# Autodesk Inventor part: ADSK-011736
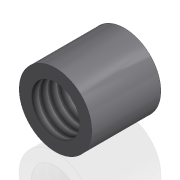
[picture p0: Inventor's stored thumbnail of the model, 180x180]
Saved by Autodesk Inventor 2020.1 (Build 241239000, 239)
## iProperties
Created: 1999-11
Part Number: ADSK-011736
Material: Acier doux
Description: HELICOIL,0.375-16NCX0.375
Document SubType Name: Modeling
Designer: lnowak
Density: 7.86 g/cm^3
Appearance: Metal-Steel(Polish)
Mass: 3.27345 g
Surface Area: 5.8451 cm^2
Volume: 0.416469 cm^3
Control State: 0
Checked Out: False
Last Check In By: lnowak
Master: False
Shininess: 0.0
Length Units: 11269
Angle Units: 11279
Time Units: 11290
Mass Units: 11283
Length Display Precision: 3
Angle Display Precision: 2
Compacted: True
Material Desc: HELICOIL, 0.375-16NC X 0.38
Material_number: A092959
Dimensions: 10x9,5x10 mm
Mass: 0,003 kg
DocNumber: ADSK-011736.ipt
Folder: 01 - Themengebiete\Simplification\01 - Packaging machine\
VDS_Category: 3D Komponenten
VLT_Material: Acier doux
Density: 0.0
Volumn: 0.0
Area: 0.0
PropertySet Name: Model Information
Author: lnowak
Revision Number: -
Title: Heli coil
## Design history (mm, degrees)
node "Solide1"
  node "Extrusion1" dims "d0" = 9.5, "d1" = 0
  node "Hole1" dims "d2" = 6.647, "d3" = 9.525, "d4" = 6.35, "d5" = 60 deg, "d6" = 22.1996, "d7" = 118 deg, "d9" = 16.002
sketch "Sketch1"
  geometry: C1 r 5 at (-23.368, 42.862)
  constraints: 1 centre point, 1 other
  dimensions: "d8" = 10 diameter of C1
node "Corps solides"
node "Corps surfaciques"
sketch "Sketch2"
  geometry: C1 r 5 at (0, 0) reference; 1 further point
  constraints: 1 coincident
